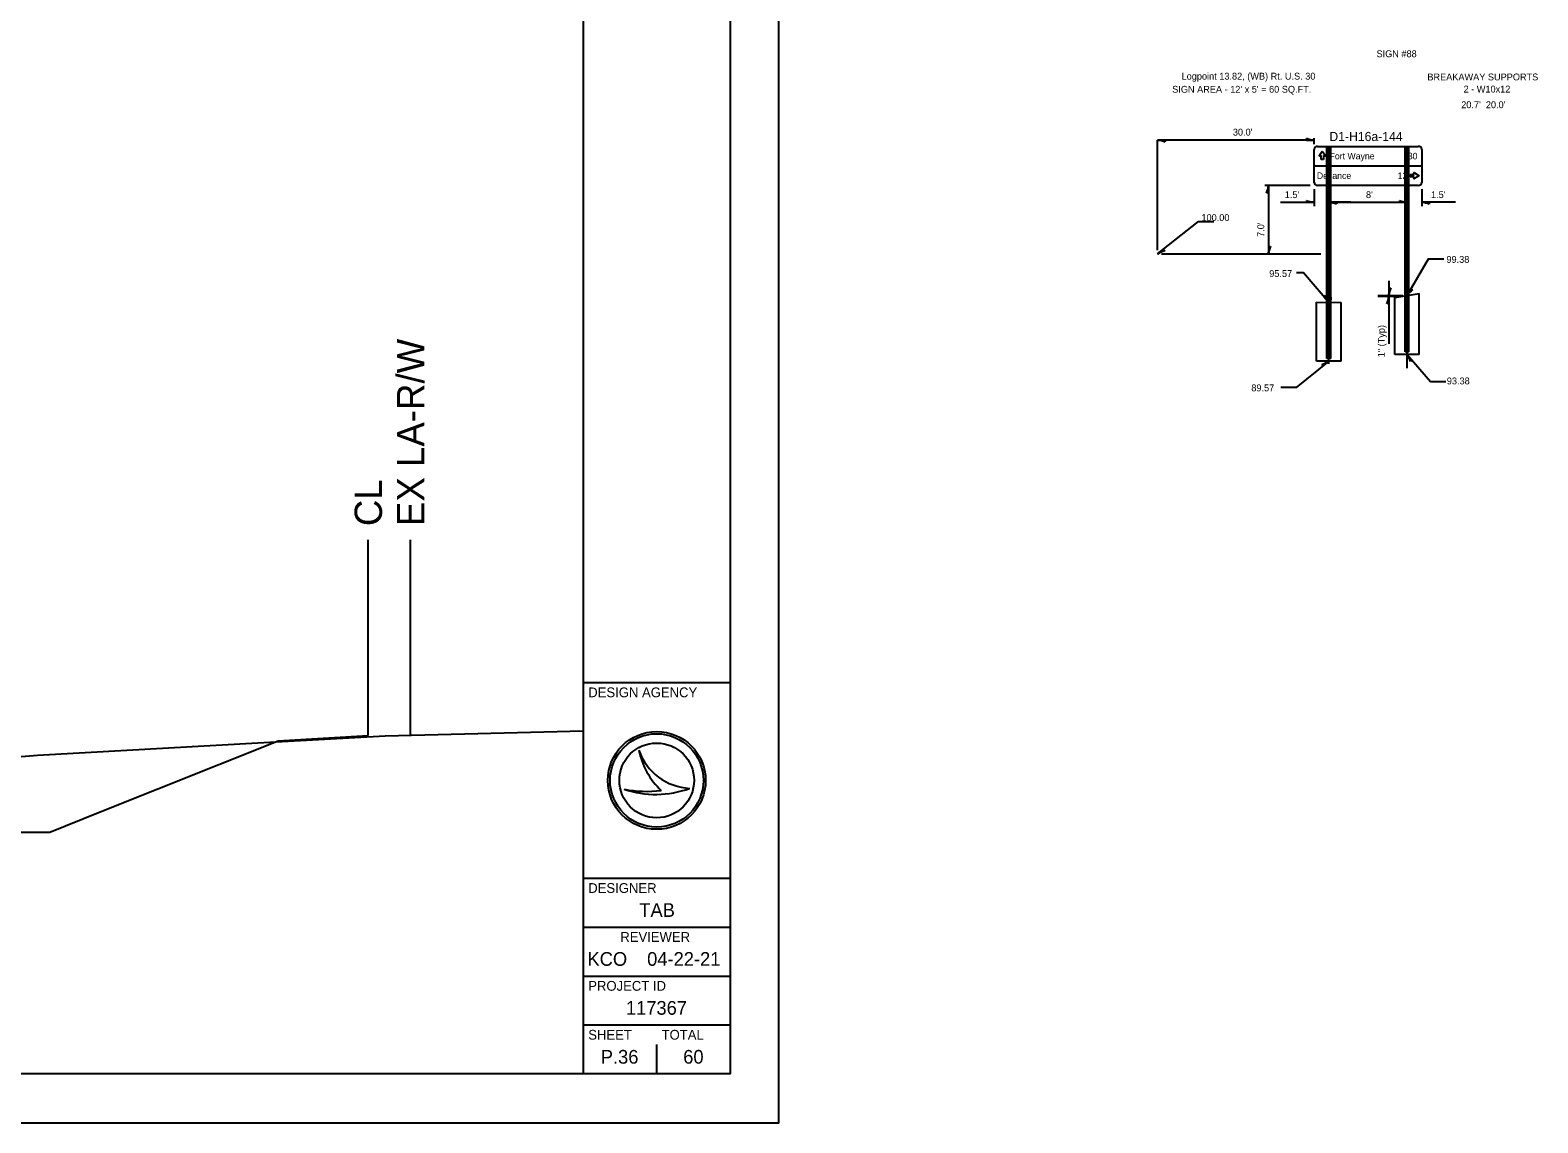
# Model space of a CAD drawing. Extents: x 0 to 418, y 0 to 220.
# Drawn here: x 263.4 to 417.6, y 0 to 111.7 of the extents above; entities that cross this region are included whole.
import ezdxf

# ---------------------------------------------------------------- set-up
doc = ezdxf.new("R2010")
doc.units = 0
for name, color, linetype in [('Default', 7, 'Continuous'), ('DR_X_Text', 7, 'Continuous'), ('MD_P_Surface_Aggregate_Base', 7, 'Continuous'), ('RW_P_Const_Limits', 7, 'Continuous'), ('SC_Scratch1', 7, 'Continuous'), ('SH_Cut_Line', 7, 'Continuous'), ('SH_Data', 7, 'Continuous'), ('SH_Named_Boundary', 7, 'Continuous'), ('XS_P_Curb', 7, 'Continuous'), ('XS_P_Finished_Grade', 7, 'Continuous'), ('XS_P_Special_Benching', 7, 'Continuous')]:
    doc.layers.add(name, color=color, linetype=linetype)

# ---------------------------------------------------------------- blocks, each defined once
blk = doc.blocks.new('AHEAD')
at = {"layer": 'Default'}
for p, q in [((-1, 0), (0, 0)), ((0, 0), (-0.97, 0.08))]:
    blk.add_line(p, q, dxfattribs=at)
for centre, radius, start, end in [((0.35, 3.54), 3.55, 247.627, 264.3005), ((-1.19, 0.13), 0.228, 326.7099, 33.2658)]:
    blk.add_arc(centre, radius, start, end, dxfattribs=at)

msp = doc.modelspace()

# ---------------------------------------------------------------- linework, layer by layer
at = {"layer": 'Default'}
for p, q in [((394.72, 100.44), (378.72, 100.44)), ((378.72, 89.2), (378.72, 100.44)), ((394.72, 100.03), (394.72, 100.66)), ((396.02, 95.81), (396.02, 99.81)), ((396.22, 77.58), (396.22, 99.81)), ((396.42, 95.81), (396.42, 99.81)), ((404.02, 95.81), (404.02, 99.81)), ((404.22, 77.14), (404.22, 99.81)), ((404.42, 95.81), (404.42, 99.81)), ((394.33, 95.81), (389.68, 95.81)), ((390.05, 95.81), (390.05, 88.81)), ((396.02, 78.11), (396.02, 95.81)), ((396.42, 78.11), (396.42, 95.81)), ((404.02, 78.79), (404.02, 95.81)), ((404.42, 78.79), (404.42, 95.81)), ((391.27, 94.09), (394.72, 94.09)), ((394.72, 95.42), (394.72, 93.7)), ((396.22, 94.09), (404.22, 94.09)), ((398.48, 94.09), (396.92, 94.09)), ((405.72, 95.42), (405.72, 93.7)), ((409.18, 94.09), (405.72, 94.09)), ((379.33, 89.3), (378.72, 88.81)), ((378.72, 88.81), (379.35, 89.23)), ((379.11, 88.81), (395.39, 88.81)), ((402.36, 86.07), (402.36, 84.58)), ((404.52, 84.96), (403.92, 84.96)), ((404.52, 84.88), (403.92, 84.88)), ((404.61, 85.25), (404.22, 84.58)), ((404.22, 84.58), (404.66, 85.2)), ((394.97, 77.86), (394.97, 83.89)), ((394.97, 83.89), (397.47, 83.84)), ((395.72, 84.46), (396.22, 83.86)), ((396.22, 83.86), (395.79, 84.48)), ((396.52, 84.28), (395.92, 84.28)), ((396.52, 84.19), (395.92, 84.19)), ((397.47, 77.86), (397.47, 83.84)), ((401.22, 84.58), (403.78, 84.58)), ((401.22, 84.49), (403.6, 84.49)), ((402.36, 84.49), (402.36, 79.61)), ((402.97, 84.37), (405.47, 84.78)), ((402.97, 78.54), (402.97, 84.37)), ((405.47, 78.54), (405.47, 84.78)), ((404.42, 78.79), (404.02, 78.79)), ((397.47, 77.86), (394.97, 77.86)), ((396.22, 77.86), (395.59, 77.43)), ((395.61, 77.37), (396.22, 77.86)), ((396.42, 78.11), (396.02, 78.11)), ((405.47, 78.54), (402.97, 78.54)), ((404.73, 77.95), (404.22, 78.54)), ((404.22, 78.54), (404.67, 77.93))]:
    msp.add_line(p, q, dxfattribs=at)
for points in [[(378.72, 88.81), (382.89, 92.14), (384.45, 92.14)], [(404.22, 84.58), (406.43, 88.32), (407.99, 88.32)], [(396.22, 83.86), (393.65, 86.87), (392.92, 86.87)], [(396.22, 77.86), (392.89, 75.16), (391.33, 75.16)], [(404.22, 78.54), (406.62, 75.79), (408.18, 75.79)]]:
    msp.add_lwpolyline(points, dxfattribs=at)
for centre, radius, start, end in [((380.23, 86.48), 2.77, 106.2378, 122.9114), ((379.51, 89.31), 0.178, 185.3207, 251.8766), ((406.46, 82.94), 2.77, 127.265, 143.9385), ((404.77, 85.33), 0.178, 206.3478, 272.9037), ((395.7, 84.64), 0.178, 276.4662, 343.0221), ((398.52, 85.41), 2.77, 197.3833, 214.0568), ((394.7, 80.18), 2.77, 286.6587, 303.3323), ((395.44, 77.35), 0.178, 5.7416, 72.2975), ((401.96, 76.94), 2.77, 18.6536, 35.3272), ((404.76, 77.78), 0.178, 97.7365, 164.2924)]:
    msp.add_arc(centre, radius, start, end, dxfattribs=at)
at = {"layer": 'DR_X_Text'}
for p, q in [((394.72, 96.13), (394.72, 99.49)), ((395.07, 99.81), (405.37, 99.81)), ((395.07, 99.81), (395.07, 99.81)), ((395.23, 98.89), (395.56, 99.31)), ((395.43, 98.87), (395.28, 98.83)), ((395.43, 98.48), (395.43, 98.87)), ((395.43, 98.87), (395.43, 98.87)), ((395.47, 98.81), (395.47, 98.81)), ((395.56, 99.31), (395.88, 98.89)), ((395.83, 98.83), (395.68, 98.87)), ((405.72, 99.49), (405.72, 96.13)), ((394.72, 97.81), (405.72, 97.81)), ((395.68, 98.48), (395.43, 98.48)), ((405.37, 95.81), (395.07, 95.81)), ((404.53, 96.7), (404.53, 96.92)), ((404.53, 96.92), (404.96, 96.92)), ((404.96, 96.92), (404.91, 97.06)), ((404.91, 96.56), (404.96, 96.7)), ((404.96, 96.92), (404.96, 96.92)), ((404.97, 96.81), (404.97, 96.81)), ((404.98, 97.1), (405.45, 96.81)), ((405.45, 96.81), (404.98, 96.52))]:
    msp.add_line(p, q, dxfattribs=at)
for points in [[(395.68, 98.87), (395.68, 98.48)], [(404.96, 96.7), (404.53, 96.7)]]:
    msp.add_lwpolyline(points, dxfattribs=at)
for centre, major_axis, start_param, end_param in [((395.07, 99.49), (-0.352, 0), 4.712389, 6.283185), ((395.27, 98.87), (-0.0476, 0), 5.670937, 8.161819), ((395.84, 98.87), (-0.0476, 0), 1.262959, 3.753841), ((405.37, 99.49), (-0.352, 0), 3.141593, 4.712389), ((395.07, 96.13), (0.352, 0), 3.141593, 4.712389), ((404.96, 97.07), (0.0476, 0), 0.958548, 3.44943), ((404.96, 96.55), (0.0476, 0), 2.833755, 5.324637), ((405.37, 96.13), (0.352, 0), 4.712389, 6.283185)]:
    msp.add_ellipse(centre, major_axis=major_axis, ratio=0.909091, start_param=start_param, end_param=end_param, dxfattribs=at)
at = {"layer": 'MD_P_Surface_Aggregate_Base'}
msp.add_line((302.34, 39.6), (302.34, 59.6), dxfattribs=at)
at = {"layer": 'SC_Scratch1'}
msp.add_lwpolyline([(250.89, 36.48), (264.18, 37.59), (286.71, 38.84), (299.74, 39.54), (320, 40.08)], dxfattribs=at)
at = {"layer": 'SH_Cut_Line'}
for p, q in [((325.67, 38.1), (325.67, 38.1)), ((324.17, 34.1), (324.17, 34.1)), ((327.5, 35), (327.5, 35)), ((330.87, 34.19), (330.87, 34.19)), ((327.5, 5), (327.5, 8)), ((323.75, 6.75), (323.75, 6.75))]:
    msp.add_line(p, q, dxfattribs=at)
for radius in [5, 4.77, 4.77, 3.82]:
    msp.add_circle((327.5, 35), radius, dxfattribs=at)
for centre, radius, start, end in [((331.16, 39.98), 5.8, 198.9257, 198.9319), ((333.47, 39.7), 7.96, 191.6379, 191.6421), ((331.16, 39.98), 5.8, 198.9319, 267.1657), ((333.47, 39.7), 7.96, 191.6421, 226.0947), ((327.39, 43.7), 10.13, 251.4576, 290.0832), ((326.48, 46.54), 12.66, 259.4964, 259.4995), ((327.39, 43.7), 10.13, 251.4527, 251.4576), ((326.48, 46.54), 12.66, 259.4995, 276.6672)]:
    msp.add_arc(centre, radius, start, end, dxfattribs=at)
at = {"layer": 'SH_Data'}
for p, q in [((320, 5), (320, 215)), ((320, 45), (335, 45)), ((320, 25), (335, 25)), ((320, 20), (335, 20)), ((320, 15), (335, 15)), ((320, 10), (335, 10))]:
    msp.add_line(p, q, dxfattribs=at)
msp.add_lwpolyline([(15, 215), (335, 215), (335, 5), (15, 5)], close=True, dxfattribs=at)
at = {"layer": 'SH_Named_Boundary'}
msp.add_lwpolyline([(0, 0), (340, 0), (340, 220), (0, 220)], close=True, dxfattribs=at)
at = {"layer": 'XS_P_Curb'}
msp.add_line((288.81, 39.06), (298.01, 39.59), dxfattribs=at)
msp.add_lwpolyline([(265.43, 29.71), (270.43, 31.71), (288.81, 39.06)], dxfattribs=at)
at = {"layer": 'XS_P_Finished_Grade'}
msp.add_line((261.43, 29.71), (265.43, 29.71), dxfattribs=at)
at = {"layer": 'XS_P_Special_Benching'}
msp.add_line((298.01, 39.59), (298.01, 59.59), dxfattribs=at)

# ---------------------------------------------------------------- block references
at = {"layer": 'Default', "xscale": 0.7799350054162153, "yscale": 0.7802600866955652}
for p, rotation in [((378.72, 100.44), 180), ((390.05, 95.81), 90), ((396.22, 94.09), 180), ((405.72, 94.09), 180), ((390.05, 88.81), -90), ((402.36, 84.58), -90), ((402.36, 84.49), 90)]:
    msp.add_blockref('AHEAD', p, dxfattribs=dict(at, rotation=rotation))
for p in [(394.72, 100.44), (394.72, 94.09), (404.22, 94.09)]:
    msp.add_blockref('AHEAD', p, dxfattribs=at)

# ---------------------------------------------------------------- texts
at = {"layer": 'Default'}
for s, p in [('SIGN #88', (401.1, 108.92)), ('Logpoint 13.82, (WB) Rt. U.S. 30', (381.17, 106.63)), ('BREAKAWAY SUPPORTS', (406.3, 106.55)), ("SIGN AREA - 12' x 5' = 60 SQ.FT.", (380.21, 105.29)), ('2 - W10x12', (410, 105.31)), ("20.7'  20.0'", (409.76, 103.71)), ("30.0'", (386.41, 100.91)), ("1.5'", (391.72, 94.52)), ("8'", (400.02, 94.52)), ("1.5'", (406.67, 94.52)), ('100.00', (383.2, 92.18)), ('99.38', (408.25, 87.9)), ('95.57', (390.13, 86.46)), ('93.38', (408.29, 75.48)), ('89.57', (388.3, 74.77))]:
    msp.add_text(s, height=0.7, dxfattribs=at).set_placement(p)
for s, p in [("7.0'", (389.62, 90.55)), ('1" (Typ)', (401.94, 78.25))]:
    msp.add_text(s, height=0.7, rotation=90, dxfattribs=at).set_placement(p)
at = {"layer": 'DR_X_Text'}
for s, p in [('Fort Wayne', (396.3, 98.48)), ('30', (404.3, 98.48)), ('Defiance', (395, 96.48)), ('12', (403.26, 96.48))]:
    msp.add_text(s, height=0.666, dxfattribs=at).set_placement(p)
at = {"layer": 'MD_P_Surface_Aggregate_Base'}
msp.add_text('EX LA-R/W', height=2.8, rotation=90, dxfattribs=at).set_placement((303.74, 61))
at = {"layer": 'RW_P_Const_Limits'}
msp.add_text('D1-H16a-144', height=0.9333, dxfattribs=at).set_placement((396.28, 100.35))
at = {"layer": 'SH_Cut_Line'}
for s, height, p in [('DESIGN AGENCY', 1, (320.5, 43.5)), ('DESIGNER', 1, (320.5, 23.5)), ('TAB', 1.4, (325.72, 21.05)), ('REVIEWER', 1, (323.78, 18.5)), ('KCO', 1.4, (320.42, 16.05)), ('04-22-21', 1.4, (326.52, 16.05)), ('PROJECT ID', 1, (320.5, 13.5)), ('117367', 1.4, (324.35, 11.05)), ('SHEET', 1, (320.5, 8.5)), ('TOTAL', 1, (328, 8.5)), ('P.36', 1.4, (321.78, 6.05)), ('60', 1.4, (330.21, 6.05))]:
    msp.add_text(s, height=height, dxfattribs=at).set_placement(p)
at = {"layer": 'XS_P_Special_Benching'}
msp.add_text('CL', height=2.8, rotation=90, dxfattribs=at).set_placement((299.41, 60.99))

doc.saveas('drawing.dxf')
